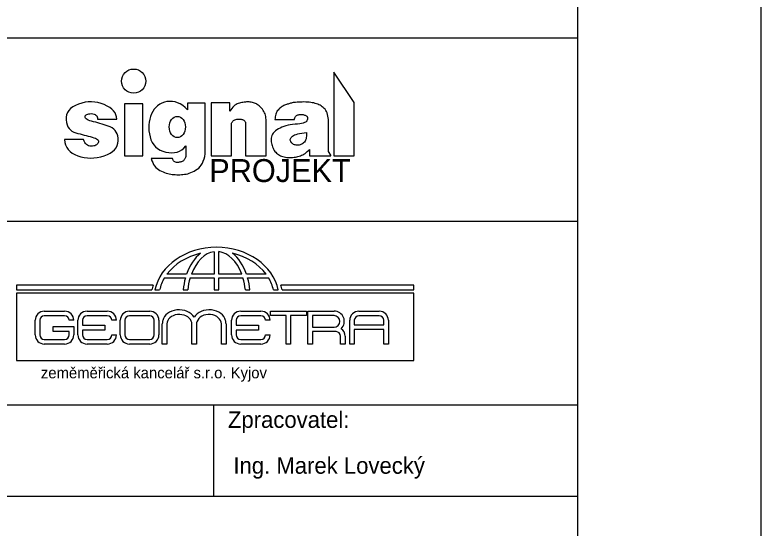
# Model space of a CAD drawing. Extents: x 3181 to 4881, y -2428 to -1984.
# Drawn here: x 4054.2 to 4135.6, y -2329.3 to -2273.3 of the extents above; entities that cross this region are included whole.
import ezdxf

# ---------------------------------------------------------------- set-up
doc = ezdxf.new("R2010")
doc.units = 0
for name, color, linetype in [('Default', 7, 'Continuous'), ('Vrstva 1', 7, 'Continuous'), ('Vrstva 11', 7, 'Continuous'), ('Vrstva 17', 7, 'Continuous'), ('Vrstva 6', 7, 'Continuous')]:
    doc.layers.add(name, color=color, linetype=linetype)

msp = doc.modelspace()

# ---------------------------------------------------------------- linework, layer by layer
at = {"layer": 'Default'}
msp.add_lwpolyline([(3925.563, -2427.81), (4135.563, -2427.81), (4135.563, -2130.81), (3925.563, -2130.81)], close=True, dxfattribs=at)
at = {"layer": 'Vrstva 1'}
msp.add_lwpolyline([(3945.563, -2150.81), (4115.563, -2150.81), (4115.563, -2410.81), (3945.563, -2410.81)], close=True, dxfattribs=at)
at = {"layer": 'Vrstva 11'}
for points in [[(4091.228, -2288.689), (4091.228, -2282.849), (4088.988, -2279.569), (4088.988, -2288.689), (4091.228, -2288.689)], [(4062.499, -2288.924), (4062.861, -2288.908), (4063.228, -2288.86), (4063.599, -2288.781), (4063.975, -2288.67), (4064.329, -2288.534), (4064.637, -2288.378), (4064.898, -2288.202), (4065.112, -2288.006), (4065.28, -2287.79), (4065.4, -2287.554), (4065.474, -2287.298), (4065.5, -2287.023), (4065.49, -2286.749), (4065.451, -2286.5), (4065.385, -2286.276), (4065.291, -2286.077), (4065.17, -2285.902), (4065.021, -2285.752), (4064.844, -2285.626), (4064.639, -2285.526), (4064.42, -2285.44), (4064.198, -2285.358), (4063.973, -2285.28), (4063.747, -2285.207), (4063.518, -2285.139), (4063.287, -2285.075), (4063.054, -2285.015), (4062.818, -2284.96), (4062.596, -2284.905), (4062.405, -2284.846), (4062.244, -2284.783), (4062.114, -2284.715), (4062.014, -2284.644), (4061.945, -2284.569), (4061.906, -2284.49), (4061.897, -2284.407), (4061.914, -2284.327), (4061.95, -2284.259), (4062.006, -2284.201), (4062.082, -2284.153), (4062.178, -2284.117), (4062.294, -2284.092), (4062.429, -2284.077), (4062.585, -2284.073), (4062.74, -2284.084), (4062.875, -2284.113), (4062.99, -2284.161), (4063.085, -2284.226), (4063.16, -2284.31), (4063.214, -2284.412), (4063.249, -2284.533), (4063.263, -2284.671), (4065.342, -2284.671), (4065.323, -2284.43), (4065.261, -2284.2), (4065.156, -2283.983), (4065.008, -2283.779), (4064.817, -2283.587), (4064.583, -2283.408), (4064.307, -2283.242), (4063.987, -2283.089), (4063.645, -2282.959), (4063.3, -2282.865), (4062.952, -2282.805), (4062.602, -2282.78), (4062.249, -2282.79), (4061.894, -2282.835), (4061.535, -2282.915), (4061.174, -2283.029), (4060.836, -2283.172), (4060.547, -2283.334), (4060.306, -2283.518), (4060.114, -2283.722), (4059.971, -2283.946), (4059.876, -2284.191), (4059.83, -2284.456), (4059.832, -2284.742), (4059.872, -2285.024), (4059.938, -2285.276), (4060.03, -2285.498), (4060.148, -2285.691), (4060.293, -2285.854), (4060.464, -2285.988), (4060.661, -2286.092), (4060.885, -2286.167), (4061.12, -2286.227), (4061.351, -2286.287), (4061.578, -2286.346), (4061.802, -2286.405), (4062.023, -2286.463), (4062.239, -2286.522), (4062.452, -2286.58), (4062.662, -2286.638), (4062.854, -2286.698), (4063.016, -2286.762), (4063.146, -2286.831), (4063.246, -2286.904), (4063.314, -2286.982), (4063.352, -2287.065), (4063.359, -2287.151), (4063.335, -2287.243), (4063.289, -2287.331), (4063.228, -2287.407), (4063.152, -2287.472), (4063.062, -2287.525), (4062.958, -2287.566), (4062.84, -2287.596), (4062.707, -2287.615), (4062.559, -2287.621), (4062.411, -2287.611), (4062.275, -2287.578), (4062.152, -2287.522), (4062.04, -2287.444), (4061.942, -2287.342), (4061.855, -2287.219), (4061.781, -2287.072), (4061.72, -2286.904), (4059.639, -2286.904), (4059.683, -2287.21), (4059.767, -2287.492), (4059.89, -2287.75), (4060.052, -2287.984), (4060.254, -2288.194), (4060.496, -2288.379), (4060.778, -2288.54), (4061.099, -2288.676), (4061.442, -2288.785), (4061.79, -2288.863), (4062.142, -2288.909), (4062.499, -2288.924)], [(4068.188, -2288.689), (4068.188, -2283.009), (4066.188, -2283.009), (4066.188, -2288.689), (4068.188, -2288.689)], [(4072.047, -2290.731), (4072.216, -2290.728), (4072.386, -2290.719), (4072.558, -2290.706), (4072.731, -2290.687), (4072.905, -2290.661), (4073.079, -2290.622), (4073.253, -2290.57), (4073.426, -2290.507), (4073.6, -2290.432), (4073.772, -2290.344), (4073.945, -2290.244), (4074.117, -2290.132), (4074.282, -2290.003), (4074.43, -2289.85), (4074.563, -2289.674), (4074.679, -2289.475), (4074.78, -2289.253), (4074.865, -2289.008), (4074.934, -2288.74), (4074.988, -2288.449), (4074.988, -2282.929), (4073.068, -2282.929), (4073.068, -2283.649), (4072.802, -2283.395), (4072.531, -2283.182), (4072.257, -2283.009), (4071.978, -2282.878), (4071.695, -2282.789), (4071.407, -2282.74), (4071.116, -2282.732), (4070.82, -2282.766), (4070.533, -2282.834), (4070.267, -2282.931), (4070.024, -2283.056), (4069.802, -2283.21), (4069.602, -2283.392), (4069.423, -2283.603), (4069.267, -2283.843), (4069.132, -2284.11), (4069.022, -2284.396), (4068.937, -2284.689), (4068.878, -2284.989), (4068.845, -2285.297), (4068.838, -2285.611), (4068.857, -2285.933), (4068.901, -2286.262), (4068.972, -2286.598), (4069.072, -2286.921), (4069.205, -2287.212), (4069.37, -2287.47), (4069.568, -2287.696), (4069.799, -2287.888), (4070.062, -2288.048), (4070.358, -2288.176), (4070.687, -2288.27), (4071.023, -2288.328), (4071.342, -2288.346), (4071.643, -2288.322), (4071.926, -2288.258), (4072.191, -2288.154), (4072.438, -2288.008), (4072.668, -2287.822), (4072.88, -2287.595), (4072.88, -2288.672), (4072.861, -2288.759), (4072.838, -2288.841), (4072.81, -2288.917), (4072.778, -2288.987), (4072.742, -2289.052), (4072.701, -2289.11), (4072.655, -2289.163), (4072.605, -2289.211), (4072.55, -2289.252), (4072.487, -2289.289), (4072.417, -2289.32), (4072.34, -2289.345), (4072.256, -2289.365), (4072.165, -2289.38), (4072.067, -2289.389), (4071.962, -2289.393), (4071.858, -2289.388), (4071.765, -2289.369), (4071.682, -2289.338), (4071.609, -2289.292), (4071.546, -2289.234), (4071.493, -2289.163), (4071.451, -2289.078), (4071.418, -2288.98), (4069.111, -2288.98), (4069.18, -2289.207), (4069.264, -2289.416), (4069.361, -2289.606), (4069.472, -2289.778), (4069.596, -2289.93), (4069.735, -2290.064), (4069.887, -2290.179), (4070.053, -2290.276), (4070.225, -2290.359), (4070.396, -2290.433), (4070.565, -2290.498), (4070.733, -2290.555), (4070.899, -2290.604), (4071.064, -2290.643), (4071.227, -2290.675), (4071.389, -2290.697), (4071.551, -2290.713), (4071.715, -2290.724), (4071.88, -2290.73), (4072.047, -2290.731)], [(4081.628, -2288.689), (4081.628, -2284.889), (4081.624, -2284.719), (4081.61, -2284.556), (4081.586, -2284.399), (4081.55, -2284.249), (4081.504, -2284.106), (4081.447, -2283.969), (4081.379, -2283.839), (4081.301, -2283.715), (4081.216, -2283.599), (4081.129, -2283.491), (4081.04, -2283.391), (4080.949, -2283.299), (4080.856, -2283.216), (4080.761, -2283.14), (4080.664, -2283.073), (4080.565, -2283.014), (4080.462, -2282.963), (4080.356, -2282.919), (4080.245, -2282.882), (4080.13, -2282.851), (4080.011, -2282.828), (4079.887, -2282.811), (4079.759, -2282.801), (4079.627, -2282.799), (4079.493, -2282.802), (4079.361, -2282.81), (4079.229, -2282.823), (4079.099, -2282.841), (4078.97, -2282.864), (4078.842, -2282.892), (4078.716, -2282.924), (4078.59, -2282.962), (4078.467, -2283.01), (4078.345, -2283.075), (4078.226, -2283.156), (4078.11, -2283.254), (4077.996, -2283.368), (4077.884, -2283.499), (4077.775, -2283.646), (4077.668, -2283.809), (4077.668, -2282.889), (4075.628, -2282.889), (4075.628, -2288.689), (4077.868, -2288.689), (4077.868, -2285.129), (4077.902, -2285.038), (4077.946, -2284.957), (4078.001, -2284.886), (4078.065, -2284.825), (4078.139, -2284.774), (4078.223, -2284.733), (4078.317, -2284.702), (4078.421, -2284.681), (4078.527, -2284.668), (4078.628, -2284.661), (4078.723, -2284.66), (4078.814, -2284.666), (4078.899, -2284.677), (4078.978, -2284.695), (4079.053, -2284.718), (4079.122, -2284.748), (4079.184, -2284.783), (4079.238, -2284.821), (4079.284, -2284.863), (4079.321, -2284.909), (4079.35, -2284.959), (4079.371, -2285.012), (4079.383, -2285.069), (4079.388, -2285.129), (4079.388, -2288.689), (4081.628, -2288.689)], [(4084.19, -2288.853), (4084.352, -2288.85), (4084.51, -2288.842), (4084.663, -2288.827), (4084.812, -2288.807), (4084.956, -2288.782), (4085.097, -2288.75), (4085.233, -2288.713), (4085.364, -2288.67), (4085.493, -2288.618), (4085.62, -2288.557), (4085.746, -2288.485), (4085.869, -2288.403), (4085.991, -2288.31), (4086.112, -2288.207), (4086.23, -2288.093), (4086.348, -2287.969), (4086.348, -2288.689), (4088.668, -2288.689), (4088.668, -2288.609), (4088.428, -2288.209), (4088.428, -2284.729), (4088.401, -2284.525), (4088.365, -2284.334), (4088.32, -2284.159), (4088.265, -2283.998), (4088.201, -2283.851), (4088.127, -2283.718), (4088.043, -2283.601), (4087.95, -2283.497), (4087.849, -2283.405), (4087.742, -2283.319), (4087.628, -2283.24), (4087.508, -2283.168), (4087.382, -2283.103), (4087.25, -2283.045), (4087.111, -2282.994), (4086.966, -2282.95), (4086.814, -2282.912), (4086.655, -2282.88), (4086.489, -2282.853), (4086.315, -2282.832), (4086.135, -2282.817), (4085.947, -2282.808), (4085.751, -2282.804), (4085.549, -2282.806), (4085.35, -2282.813), (4085.166, -2282.821), (4084.997, -2282.831), (4084.843, -2282.844), (4084.703, -2282.859), (4084.578, -2282.876), (4084.467, -2282.896), (4084.372, -2282.917), (4084.283, -2282.941), (4084.194, -2282.967), (4084.104, -2282.994), (4084.013, -2283.024), (4083.921, -2283.055), (4083.829, -2283.089), (4083.737, -2283.124), (4083.643, -2283.162), (4083.55, -2283.203), (4083.458, -2283.252), (4083.366, -2283.307), (4083.276, -2283.369), (4083.187, -2283.438), (4083.099, -2283.514), (4083.012, -2283.597), (4082.926, -2283.686), (4082.845, -2283.784), (4082.776, -2283.891), (4082.718, -2284.007), (4082.67, -2284.133), (4082.633, -2284.268), (4082.607, -2284.412), (4082.592, -2284.566), (4082.588, -2284.729), (4084.708, -2284.729), (4084.723, -2284.633), (4084.747, -2284.546), (4084.78, -2284.468), (4084.821, -2284.399), (4084.872, -2284.339), (4084.93, -2284.288), (4084.998, -2284.247), (4085.073, -2284.215), (4085.154, -2284.191), (4085.235, -2284.173), (4085.317, -2284.161), (4085.399, -2284.157), (4085.481, -2284.158), (4085.565, -2284.167), (4085.648, -2284.181), (4085.732, -2284.203), (4085.813, -2284.228), (4085.884, -2284.256), (4085.947, -2284.286), (4086, -2284.318), (4086.045, -2284.352), (4086.082, -2284.388), (4086.109, -2284.427), (4086.128, -2284.467), (4086.14, -2284.51), (4086.145, -2284.556), (4086.144, -2284.605), (4086.136, -2284.656), (4086.122, -2284.71), (4086.103, -2284.767), (4086.076, -2284.827), (4086.044, -2284.89), (4085.993, -2284.951), (4085.912, -2285.007), (4085.801, -2285.057), (4085.659, -2285.103), (4085.487, -2285.143), (4085.285, -2285.178), (4085.052, -2285.207), (4084.789, -2285.231), (4084.517, -2285.258), (4084.258, -2285.295), (4084.01, -2285.343), (4083.775, -2285.402), (4083.553, -2285.471), (4083.342, -2285.55), (4083.144, -2285.64), (4082.958, -2285.741), (4082.789, -2285.849), (4082.641, -2285.962), (4082.513, -2286.079), (4082.407, -2286.201), (4082.321, -2286.327), (4082.256, -2286.457), (4082.212, -2286.593), (4082.189, -2286.732), (4082.181, -2286.874), (4082.182, -2287.014), (4082.192, -2287.153), (4082.211, -2287.291), (4082.239, -2287.427), (4082.276, -2287.563), (4082.322, -2287.697), (4082.377, -2287.83), (4082.44, -2287.958), (4082.51, -2288.078), (4082.587, -2288.188), (4082.671, -2288.29), (4082.761, -2288.382), (4082.859, -2288.466), (4082.964, -2288.541), (4083.075, -2288.607), (4083.193, -2288.665), (4083.317, -2288.715), (4083.447, -2288.757), (4083.584, -2288.792), (4083.726, -2288.819), (4083.875, -2288.838), (4084.03, -2288.849), (4084.19, -2288.853)], [(4084.906, -2287.509), (4084.803, -2287.488), (4084.708, -2287.46), (4084.622, -2287.424), (4084.543, -2287.38), (4084.472, -2287.329), (4084.409, -2287.27), (4084.354, -2287.203), (4084.307, -2287.129), (4084.273, -2287.051), (4084.255, -2286.974), (4084.254, -2286.898), (4084.27, -2286.823), (4084.302, -2286.749), (4084.351, -2286.676), (4084.417, -2286.603), (4084.5, -2286.532), (4084.603, -2286.464), (4084.732, -2286.401), (4084.886, -2286.343), (4085.065, -2286.29), (4085.269, -2286.243), (4085.498, -2286.201), (4085.753, -2286.165), (4086.032, -2286.134), (4086.037, -2286.332), (4086.028, -2286.514), (4086.006, -2286.68), (4085.972, -2286.83), (4085.924, -2286.963), (4085.864, -2287.081), (4085.79, -2287.182), (4085.704, -2287.267), (4085.611, -2287.339), (4085.515, -2287.398), (4085.418, -2287.446), (4085.319, -2287.482), (4085.219, -2287.506), (4085.116, -2287.519), (4085.012, -2287.52), (4084.906, -2287.509)]]:
    msp.add_lwpolyline(points, dxfattribs=at)
msp.add_circle((4067.188, -2280.529), 1.32, dxfattribs=at)
msp.add_ellipse((4071.948, -2285.529), major_axis=(0, 1.16), ratio=0.758621, dxfattribs=at)
at = {"layer": 'Vrstva 17'}
for p, q in [((4075.958, -2299.123), (4075.958, -2301.568)), ((4076.465, -2301.568), (4076.465, -2299.12)), ((4072.965, -2301.568), (4070.82, -2301.568)), ((4075.958, -2301.568), (4073.482, -2301.568)), ((4078.96, -2301.568), (4076.465, -2301.568)), ((4081.622, -2301.568), (4079.477, -2301.568)), ((4069.314, -2302.769), (4054.433, -2302.769)), ((4054.433, -2302.769), (4054.433, -2303.3)), ((4070.545, -2301.98), (4072.832, -2301.98)), ((4073.342, -2301.98), (4075.958, -2301.98)), ((4075.958, -2301.98), (4075.958, -2303.3)), ((4076.465, -2303.3), (4076.465, -2301.98)), ((4076.465, -2301.98), (4079.099, -2301.98)), ((4079.609, -2301.98), (4081.897, -2301.98)), ((4097.712, -2302.769), (4083.233, -2302.769)), ((4097.712, -2303.3), (4097.712, -2302.769)), ((4054.433, -2303.3), (4069.176, -2303.3)), ((4069.502, -2303.3), (4070.019, -2303.3)), ((4072.575, -2303.3), (4073.075, -2303.3)), ((4075.958, -2303.3), (4076.465, -2303.3)), ((4079.366, -2303.3), (4079.866, -2303.3)), ((4082.423, -2303.3), (4082.94, -2303.3)), ((4083.371, -2303.3), (4097.712, -2303.3)), ((4097.71, -2303.645), (4054.427, -2303.645)), ((4054.427, -2303.645), (4054.427, -2310.983)), ((4097.71, -2310.983), (4097.71, -2303.645)), ((4057.452, -2305.611), (4059.663, -2305.611)), ((4062.108, -2305.611), (4064.319, -2305.611)), ((4066.732, -2305.611), (4068.943, -2305.611)), ((4078.851, -2305.611), (4081.061, -2305.611)), ((4086.188, -2305.611), (4089.032, -2305.611)), ((4091.736, -2305.611), (4093.947, -2305.611)), ((4056.454, -2308.195), (4056.454, -2306.609)), ((4056.953, -2306.609), (4056.953, -2308.195)), ((4059.663, -2306.109), (4057.452, -2306.109)), ((4060.66, -2306.609), (4060.162, -2306.609)), ((4061.11, -2308.195), (4061.11, -2306.609)), ((4061.609, -2306.609), (4061.609, -2307.119)), ((4064.319, -2306.109), (4062.108, -2306.109)), ((4065.317, -2306.609), (4064.818, -2306.609)), ((4065.734, -2308.195), (4065.734, -2306.609)), ((4066.233, -2306.609), (4066.233, -2308.195)), ((4068.943, -2306.109), (4066.732, -2306.109)), ((4069.442, -2308.195), (4069.442, -2306.609)), ((4069.941, -2306.609), (4069.941, -2308.195)), ((4077.853, -2308.195), (4077.853, -2306.609)), ((4078.352, -2306.609), (4078.352, -2307.119)), ((4081.061, -2306.109), (4078.851, -2306.109)), ((4082.059, -2306.609), (4081.56, -2306.609)), ((4083.794, -2309.193), (4083.794, -2306.097)), ((4084.297, -2306.097), (4084.297, -2309.193)), ((4089.032, -2306.1), (4086.692, -2306.1)), ((4086.692, -2306.1), (4086.692, -2307.349)), ((4090.738, -2309.193), (4090.738, -2306.609)), ((4091.237, -2306.609), (4091.237, -2307.117)), ((4093.947, -2306.109), (4091.736, -2306.109)), ((4094.446, -2307.117), (4094.446, -2306.609)), ((4094.945, -2306.609), (4094.945, -2309.193)), ((4058.427, -2307.817), (4058.427, -2307.272)), ((4058.427, -2307.272), (4060.66, -2307.272)), ((4060.66, -2307.272), (4060.66, -2308.195)), ((4061.609, -2307.119), (4064.052, -2307.119)), ((4064.052, -2307.664), (4061.609, -2307.664)), ((4061.609, -2307.664), (4061.609, -2308.195)), ((4064.052, -2307.119), (4064.052, -2307.664)), ((4070.313, -2309.193), (4070.313, -2307.008)), ((4070.814, -2307.008), (4070.814, -2309.193)), ((4073.533, -2309.193), (4073.533, -2307.008)), ((4074.033, -2307.008), (4074.033, -2309.193)), ((4076.752, -2309.193), (4076.752, -2307.008)), ((4077.253, -2307.008), (4077.253, -2309.193)), ((4078.352, -2307.119), (4080.795, -2307.119)), ((4080.795, -2307.664), (4078.352, -2307.664)), ((4078.352, -2307.664), (4078.352, -2308.195)), ((4080.795, -2307.119), (4080.795, -2307.664)), ((4086.692, -2307.349), (4089.032, -2307.349)), ((4091.237, -2307.117), (4094.446, -2307.117)), ((4094.446, -2307.621), (4091.237, -2307.621)), ((4091.237, -2307.621), (4091.237, -2309.193)), ((4094.446, -2309.193), (4094.446, -2307.621)), ((4060.162, -2307.817), (4058.427, -2307.817)), ((4060.162, -2308.195), (4060.162, -2307.817)), ((4064.818, -2308.195), (4065.317, -2308.195)), ((4081.56, -2308.195), (4082.059, -2308.195)), ((4089.032, -2307.838), (4086.692, -2307.838)), ((4089.247, -2307.842), (4089.032, -2307.838)), ((4089.746, -2309.193), (4089.746, -2308.341)), ((4090.244, -2308.341), (4090.244, -2309.193)), ((4057.452, -2308.694), (4059.663, -2308.694)), ((4059.663, -2309.193), (4057.452, -2309.193)), ((4062.108, -2308.694), (4064.319, -2308.694)), ((4064.319, -2309.193), (4062.108, -2309.193)), ((4066.732, -2308.694), (4068.943, -2308.694)), ((4068.943, -2309.193), (4066.732, -2309.193)), ((4070.814, -2309.193), (4070.313, -2309.193)), ((4074.033, -2309.193), (4073.533, -2309.193)), ((4077.253, -2309.193), (4076.752, -2309.193)), ((4078.851, -2308.694), (4081.061, -2308.694)), ((4081.061, -2309.193), (4078.851, -2309.193)), ((4084.297, -2309.193), (4083.794, -2309.193)), ((4090.244, -2309.193), (4089.746, -2309.193)), ((4091.237, -2309.193), (4090.738, -2309.193)), ((4094.945, -2309.193), (4094.446, -2309.193)), ((4054.427, -2310.983), (4097.71, -2310.983))]:
    msp.add_line(p, q, dxfattribs=at)
for points in [[(4083.794, -2306.097), (4082.096, -2306.097), (4082.096, -2305.611), (4086.009, -2305.611)], [(4086.009, -2305.611), (4086.009, -2306.097), (4084.297, -2306.097)], [(4086.692, -2307.838), (4086.692, -2309.193), (4086.188, -2309.193), (4086.188, -2305.611)]]:
    msp.add_lwpolyline(points, dxfattribs=at)
for centre, radius, start, end in [((4057.452, -2306.609), 0.998, 90, 180), ((4059.663, -2306.609), 0.998, 360, 90), ((4062.108, -2306.609), 0.998, 90, 180), ((4064.319, -2306.609), 0.998, 360, 90), ((4066.732, -2306.609), 0.998, 90, 180), ((4068.943, -2306.609), 0.998, 360, 90), ((4078.851, -2306.609), 0.998, 90, 180), ((4081.061, -2306.609), 0.998, 360, 90), ((4089.032, -2306.725), 1.114, 314.45734, 90), ((4091.736, -2306.609), 0.998, 90, 180), ((4093.947, -2306.609), 0.998, 360, 90), ((4057.452, -2306.609), 0.499, 90, 180), ((4059.663, -2306.609), 0.499, 0, 90), ((4062.108, -2306.609), 0.499, 90, 180), ((4064.319, -2306.609), 0.499, 0, 90), ((4066.732, -2306.609), 0.499, 90, 180), ((4068.943, -2306.609), 0.499, 0, 90), ((4072.25, -2307.058), 1.938, 166.96576, 178.52091), ((4072.579, -2307.072), 0.957, 3.86486, 22.41569), ((4075.266, -2307.13), 1.238, 162.61388, 174.3506), ((4075.315, -2307.058), 1.938, 1.47909, 13.03424), ((4078.851, -2306.609), 0.499, 90, 180), ((4081.061, -2306.609), 0.499, 0, 90), ((4089.032, -2306.725), 0.625, 270, 90), ((4091.736, -2306.609), 0.499, 90, 180), ((4093.947, -2306.609), 0.499, 0, 90), ((4089.247, -2308.341), 0.998, 360, 55.44734), ((4057.452, -2308.195), 0.998, 180, 270), ((4057.452, -2308.195), 0.499, 180, 270), ((4059.663, -2308.195), 0.998, 270, 0), ((4059.663, -2308.195), 0.499, 270, 0), ((4062.108, -2308.195), 0.998, 180, 270), ((4062.108, -2308.195), 0.499, 180, 270), ((4064.319, -2308.195), 0.998, 270, 0), ((4064.319, -2308.195), 0.499, 270, 0), ((4066.732, -2308.195), 0.998, 180, 270), ((4066.732, -2308.195), 0.499, 180, 270), ((4068.943, -2308.195), 0.998, 270, 0), ((4068.943, -2308.195), 0.499, 270, 0), ((4078.851, -2308.195), 0.998, 180, 270), ((4078.851, -2308.195), 0.499, 180, 270), ((4081.061, -2308.195), 0.998, 270, 0), ((4081.061, -2308.195), 0.499, 270, 0), ((4089.247, -2308.341), 0.499, 0, 90)]:
    msp.add_arc(centre, radius, start, end, dxfattribs=at)
for centre, major_axis, ratio, start_param, end_param in [((4076.221, -2304.173), (-6.804, 0), 0.811768, 3.300239, 6.124539), ((4076.221, -2304.173), (-6.296, 0), 0.804826, 4.992897, 5.743383), ((4076.221, -2304.173), (0, 5.524), 0.668443, 0.491666, 1.079789), ((4076.221, -2304.173), (0, 5.067), 0.630136, 0.08224, 1.030995), ((4076.221, -2304.173), (0, 5.067), 0.630136, 5.252191, 6.206521), ((4076.221, -2304.173), (0, 5.524), 0.668443, 5.203397, 5.79152), ((4076.221, -2304.173), (-6.296, 0), 0.804826, 3.681394, 4.431881), ((4075.895, -2304.173), (-6.804, 0), 0.811768, 6.026233, 6.124539), ((4076.221, -2304.173), (-6.296, 0), 0.804826, 5.835664, 6.110118), ((4076.221, -2304.173), (0, 5.524), 0.668443, 1.16256, 1.41215), ((4076.221, -2304.173), (0, 5.067), 0.630136, 1.123275, 1.397729), ((4076.221, -2304.173), (0, 5.067), 0.630136, 4.885456, 5.159911), ((4076.221, -2304.173), (0, 5.524), 0.668443, 4.871035, 5.120625), ((4076.221, -2304.173), (-6.296, 0), 0.804826, 3.31466, 3.589114), ((4076.653, -2304.173), (-6.804, 0), 0.811768, 3.300239, 3.398545), ((4072.142, -2306.852), (1.805, 0), 0.766187, 0.429647, 2.97338), ((4072.167, -2307.008), (1.354, 0), 0.766187, 0.29376, 3.141593), ((4075.424, -2306.852), (-1.805, 0), 0.766187, 3.309805, 5.853538), ((4075.398, -2307.008), (-1.354, 0), 0.766187, 3.141593, 6.041607)]:
    msp.add_ellipse(centre, major_axis=major_axis, ratio=ratio, start_param=start_param, end_param=end_param, dxfattribs=at)
at = {"layer": 'Vrstva 6'}
for p, q in [((3945.563, -2295.81), (4115.563, -2295.81)), ((3945.563, -2315.81), (4115.563, -2315.81)), ((4075.913, -2325.81), (4075.913, -2315.81))]:
    msp.add_line(p, q, dxfattribs=at)
msp.add_lwpolyline([(3945.563, -2275.81), (4115.563, -2275.81), (4115.563, -2325.81), (3945.563, -2325.81)], close=True, dxfattribs=at)

# ---------------------------------------------------------------- texts
at = {"layer": 'Vrstva 11'}
msp.add_text('PROJEKT', height=2.5, dxfattribs=at).set_placement((4075.428, -2291.532))
at = {"layer": 'Vrstva 17'}
msp.add_text('zeměměřická kancelář s.r.o. Kyjov', height=1.20984, dxfattribs=at).set_placement((4057.079, -2312.932))
at = {"layer": 'Vrstva 6'}
for s, p in [('Zpracovatel:', (4077.459, -2318.336)), ('Ing. Marek Lovecký', (4078.06, -2323.336))]:
    msp.add_text(s, height=1.8, dxfattribs=at).set_placement(p)

doc.saveas('drawing.dxf')
